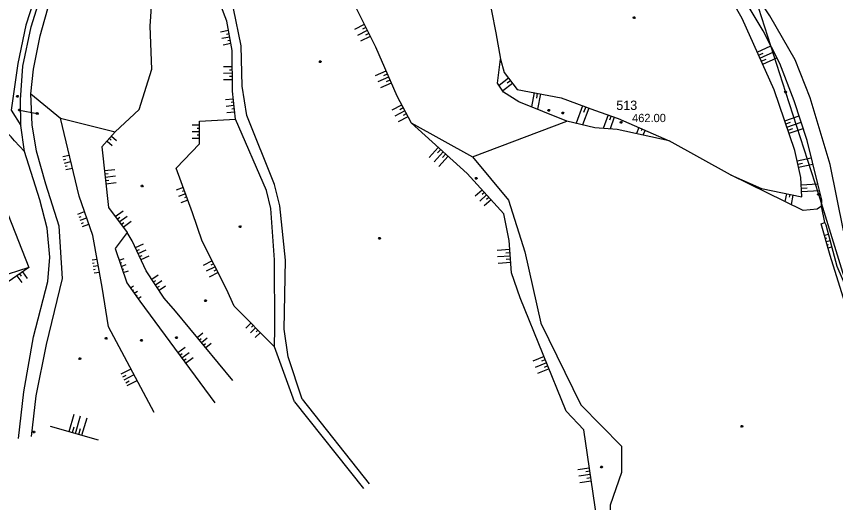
# Model space of a CAD drawing. Extents: x -664960 to -662754, y -993849 to -991145.
# Drawn here: x -664152.5 to -663855.3, y -993419.9 to -993243.5 of the extents above; entities that cross this region are included whole.
import ezdxf

# ---------------------------------------------------------------- set-up
doc = ezdxf.new("R2010")
doc.units = 0
for name, color, linetype in [('Vrstva 1', 7, 'Continuous'), ('Vrstva 13', 7, 'Continuous'), ('Vrstva 18', 7, 'Continuous'), ('Vrstva 23', 7, 'Continuous'), ('Vrstva 24', 7, 'Continuous'), ('Vrstva 27', 7, 'Continuous'), ('Vrstva 28', 7, 'Continuous'), ('Vrstva 33', 7, 'Continuous'), ('Vrstva 37', 7, 'Continuous'), ('Vrstva 57', 7, 'Continuous'), ('Vrstva 63', 7, 'Continuous'), ('Vrstva 8', 7, 'Continuous')]:
    doc.layers.add(name, color=color, linetype=linetype)

msp = doc.modelspace()

# ---------------------------------------------------------------- linework, layer by layer
at = {"layer": 'Vrstva 13'}
for points in [[(-663928.242, -993243.658), (-663928.062, -993243.958), (-663928.242, -993244.258), (-663928.602, -993244.258), (-663928.782, -993243.958), (-663928.602, -993243.658), (-663928.242, -993243.658)], [(-664042.083, -993259.608), (-664041.903, -993259.908), (-664042.083, -993260.208), (-664042.443, -993260.208), (-664042.623, -993259.908), (-664042.443, -993259.608), (-664042.083, -993259.608)], [(-664151.891, -993272.22), (-664151.711, -993272.52), (-664151.891, -993272.82), (-664152.251, -993272.82), (-664152.431, -993272.52), (-664152.251, -993272.22), (-664151.891, -993272.22)], [(-663959.185, -993277.337), (-663959.005, -993277.637), (-663959.185, -993277.937), (-663959.545, -993277.937), (-663959.725, -993277.637), (-663959.545, -993277.337), (-663959.185, -993277.337)], [(-663954.102, -993278.318), (-663953.922, -993278.618), (-663954.102, -993278.918), (-663954.462, -993278.918), (-663954.642, -993278.618), (-663954.462, -993278.318), (-663954.102, -993278.318)], [(-663985.497, -993302.005), (-663985.317, -993302.305), (-663985.497, -993302.605), (-663985.857, -993302.605), (-663986.037, -993302.305), (-663985.857, -993302.005), (-663985.497, -993302.005)], [(-664106.7, -993304.738), (-664106.52, -993305.038), (-664106.7, -993305.338), (-664107.06, -993305.338), (-664107.24, -993305.038), (-664107.06, -993304.738), (-664106.7, -993304.738)], [(-664071.171, -993319.55), (-664070.991, -993319.85), (-664071.171, -993320.15), (-664071.531, -993320.15), (-664071.711, -993319.85), (-664071.531, -993319.55), (-664071.171, -993319.55)], [(-664020.555, -993323.799), (-664020.375, -993324.099), (-664020.555, -993324.399), (-664020.915, -993324.399), (-664021.095, -993324.099), (-664020.915, -993323.799), (-664020.555, -993323.799)], [(-664106.935, -993360.698), (-664106.755, -993360.998), (-664106.935, -993361.298), (-664107.295, -993361.298), (-664107.475, -993360.998), (-664107.295, -993360.698), (-664106.935, -993360.698)], [(-664094.245, -993359.816), (-664094.065, -993360.116), (-664094.245, -993360.416), (-664094.605, -993360.416), (-664094.785, -993360.116), (-664094.605, -993359.816), (-664094.245, -993359.816)], [(-664129.266, -993367.383), (-664129.086, -993367.683), (-664129.266, -993367.983), (-664129.626, -993367.983), (-664129.806, -993367.683), (-664129.626, -993367.383), (-664129.266, -993367.383)], [(-663889.154, -993391.926), (-663888.974, -993392.226), (-663889.154, -993392.526), (-663889.514, -993392.526), (-663889.694, -993392.226), (-663889.514, -993391.926), (-663889.154, -993391.926)], [(-663940.049, -993406.702), (-663939.869, -993407.002), (-663940.049, -993407.302), (-663940.409, -993407.302), (-663940.589, -993407.002), (-663940.409, -993406.702), (-663940.049, -993406.702)]]:
    msp.add_lwpolyline(points, dxfattribs=at)
at = {"layer": 'Vrstva 18'}
msp.add_lwpolyline([(-664119.73, -993359.99), (-664119.55, -993360.29), (-664119.73, -993360.59), (-664120.09, -993360.59), (-664120.27, -993360.29), (-664120.09, -993359.99), (-664119.73, -993359.99)], dxfattribs=at)
at = {"layer": 'Vrstva 23'}
for points in [[(-663815.88, -993423.57), (-663819.75, -993405.36), (-663824.31, -993392.64), (-663830.79, -993376.07), (-663837.06, -993363.48), (-663843.01, -993348.71), (-663847.89, -993337.31), (-663852.5, -993321.23), (-663857.35, -993297.27), (-663864.53, -993273.11), (-663869.95, -993259.28), (-663879.15, -993243.34), (-663886.53, -993232.14), (-663892.56, -993221.84), (-663896.18, -993214.23), (-663900.17, -993200.79), (-663906.47, -993181.7), (-663914.77, -993161.34), (-663922.1, -993138.98)], [(-663822.04, -993421.3), (-663825.37, -993406.88), (-663827.71, -993398.5), (-663836.15, -993377.65), (-663841.61, -993365.19), (-663849.31, -993346.83), (-663854.8, -993334.21), (-663858.7, -993319.26), (-663859.27, -993318.31), (-663860.4, -993312.33), (-663860.36, -993310.06), (-663861.8, -993304.26), (-663865.7, -993288.6), (-663870.3, -993274.19), (-663875.56, -993260.56), (-663881.56, -993248.78), (-663891.79, -993231.72), (-663900.57, -993216.2), (-663905.55, -993200.84), (-663911.44, -993184.13), (-663916.56, -993171.4), (-663923.7, -993156.46)]]:
    msp.add_lwpolyline(points, dxfattribs=at)
at = {"layer": 'Vrstva 24'}
msp.add_line((-664151.4, -993277.48), (-664144.89, -993278.73), dxfattribs=at)
for points in [[(-664151.167, -993277.219), (-664151.046, -993277.548), (-664151.28, -993277.809), (-664151.633, -993277.741), (-664151.754, -993277.412), (-664151.52, -993277.151), (-664151.167, -993277.219)], [(-664144.657, -993278.469), (-664144.536, -993278.798), (-664144.77, -993279.059), (-664145.123, -993278.991), (-664145.244, -993278.662), (-664145.01, -993278.401), (-664144.657, -993278.469)]]:
    msp.add_lwpolyline(points, dxfattribs=at)
at = {"layer": 'Vrstva 27'}
for p, q in [((-664051.54, -993383.38), (-664026.58, -993414.83)), ((-664048.77, -993382.43), (-664024.46, -993413.09))]:
    msp.add_line(p, q, dxfattribs=at)
for points in [[(-664147.01, -993395.9), (-664145.28, -993381.2), (-664141.55, -993362.53), (-664135.78, -993338.59), (-664136.97, -993319.67), (-664141.74, -993304.41), (-664145.22, -993292.42), (-664146.78, -993282.88), (-664147.19, -993271.56), (-664146.28, -993262.65), (-664143.88, -993250.55), (-664140.16, -993237.45), (-664129.58, -993207.88), (-664122.4, -993183.29), (-664113.26, -993147.21), (-664109.07, -993129.57), (-664107.16, -993119.53), (-664106.79, -993108.69), (-664107.93, -993100.41), (-664112.62, -993085.27), (-664115.65, -993071.43)], [(-664051.54, -993383.38), (-664058.81, -993363.36), (-664058.78, -993356.49), (-664058.79, -993331.89), (-664060.13, -993313.2), (-664061.75, -993306.66), (-664073.02, -993280.85), (-664074.1, -993270.6), (-664074.16, -993255.88), (-664076.17, -993245.22), (-664085.19, -993221.44), (-664087.2, -993194.52), (-664081.52, -993180.73), (-664078.91, -993164.26)], [(-664048.77, -993382.43), (-664053.9, -993366.99), (-664055.33, -993357.04), (-664054.9, -993332.02), (-664056.86, -993312.19), (-664058.79, -993304.54), (-664068.83, -993279.47), (-664070.61, -993268.81), (-664070.96, -993254.16), (-664073.76, -993240.67), (-664079.2, -993222.98), (-664080.19, -993205.56), (-664079.44, -993193.25), (-664077.43, -993182.42)], [(-664151.67, -993396.63), (-664149.76, -993379.75), (-664146.27, -993359.81), (-664141.09, -993339.76), (-664140.31, -993330.82), (-664141.36, -993320.31), (-664143.91, -993310.04), (-664149.55, -993292.53), (-664150.84, -993283.04), (-664150.96, -993273.8), (-664150.15, -993261.61), (-664147.11, -993247.3), (-664143.19, -993234.78)]]:
    msp.add_lwpolyline(points, dxfattribs=at)
at = {"layer": 'Vrstva 28'}
msp.add_lwpolyline([(-664083.68, -993346.34), (-664083.5, -993346.64), (-664083.68, -993346.94), (-664084.04, -993346.94), (-664084.22, -993346.64), (-664084.04, -993346.34), (-664083.68, -993346.34)], dxfattribs=at)
at = {"layer": 'Vrstva 33'}
msp.add_lwpolyline([(-664145.96, -993394.07), (-664145.78, -993394.37), (-664145.96, -993394.67), (-664146.32, -993394.67), (-664146.5, -993394.37), (-664146.32, -993394.07), (-664145.96, -993394.07)], dxfattribs=at)
at = {"layer": 'Vrstva 37'}
for points in [[(-663873.3, -993270.68), (-663873.12, -993270.98), (-663873.3, -993271.28), (-663873.66, -993271.28), (-663873.84, -993270.98), (-663873.66, -993270.68), (-663873.3, -993270.68)], [(-663861.37, -993307.74), (-663861.19, -993308.04), (-663861.37, -993308.34), (-663861.73, -993308.34), (-663861.91, -993308.04), (-663861.73, -993307.74), (-663861.37, -993307.74)]]:
    msp.add_lwpolyline(points, dxfattribs=at)
at = {"layer": 'Vrstva 57'}
msp.add_lwpolyline([(-663937.17, -993067.28), (-663921.25, -993118.58), (-663905.79, -993167.82), (-663887.66, -993226.85), (-663873.48, -993270.98), (-663861.55, -993308.04), (-663843.55, -993366.56), (-663828.28, -993415.08), (-663809.04, -993475.6), (-663791.79, -993531.02), (-663772.5, -993592.28), (-663754.33, -993650.13), (-663735.8, -993708.15), (-663717.65, -993766.39)], dxfattribs=at)
at = {"layer": 'Vrstva 63'}
for p, q in [((-664026.288, -993246.492), (-664029.795, -993248.256)), ((-664025.748, -993247.564), (-664026.916, -993248.151)), ((-664075.52, -993248.668), (-664078.411, -993249.213)), ((-664075.075, -993251.026), (-664077.966, -993251.572)), ((-664075.298, -993249.847), (-664076.26, -993250.029)), ((-664025.209, -993248.636), (-664028.717, -993250.4)), ((-664024.131, -993250.78), (-664027.638, -993252.544)), ((-664024.67, -993249.708), (-664025.838, -993250.295)), ((-664074.63, -993253.385), (-664077.522, -993253.93)), ((-664074.853, -993252.206), (-664075.816, -993252.387)), ((-663883.748, -993256.465), (-663878.785, -993254.228)), ((-663883.255, -993257.559), (-663881.585, -993256.806)), ((-663882.761, -993258.653), (-663877.694, -993256.369)), ((-663882.268, -993259.747), (-663880.564, -993258.979)), ((-663881.775, -993260.841), (-663876.604, -993258.51)), ((-664074.136, -993261.763), (-664077.398, -993261.776)), ((-664074.131, -993262.963), (-664075.217, -993262.967)), ((-664074.126, -993264.163), (-664077.388, -993264.176)), ((-664074.121, -993265.363), (-664075.208, -993265.367)), ((-664018.417, -993263.373), (-664022.364, -993265.083)), ((-664017.463, -993265.575), (-664021.411, -993267.285)), ((-664017.94, -993264.474), (-664019.254, -993265.043)), ((-663974.005, -993265.912), (-663977.375, -993268.542)), ((-664074.116, -993266.563), (-664077.378, -993266.576)), ((-664016.509, -993267.778), (-664020.457, -993269.487)), ((-664016.986, -993266.676), (-664018.301, -993267.246)), ((-663972.529, -993267.804), (-663976.081, -993270.576)), ((-663973.267, -993266.858), (-663974.419, -993267.758)), ((-663964.695, -993271.182), (-663965.667, -993276.288)), ((-663963.517, -993271.406), (-663963.855, -993273.184)), ((-663962.338, -993271.631), (-663963.398, -993277.202)), ((-664073.796, -993273.481), (-664076.59, -993273.776)), ((-664073.671, -993274.675), (-664074.601, -993274.773)), ((-664073.545, -993275.868), (-664076.338, -993276.162)), ((-664073.419, -993277.062), (-664074.349, -993277.16)), ((-664012.752, -993275.68), (-664016.285, -993277.567)), ((-664011.621, -993277.796), (-664015.154, -993279.684)), ((-664012.186, -993276.738), (-664013.363, -993277.367)), ((-663947.088, -993275.937), (-663949.456, -993282.309)), ((-663944.838, -993276.773), (-663947.113, -993282.894)), ((-663945.963, -993276.355), (-663946.736, -993278.435)), ((-664073.293, -993278.255), (-664076.087, -993278.549)), ((-664010.49, -993279.913), (-664014.023, -993281.801)), ((-664011.055, -993278.855), (-664012.232, -993279.484)), ((-663937.883, -993279.237), (-663939.598, -993284.185)), ((-663936.749, -993279.63), (-663937.283, -993281.172)), ((-663935.615, -993280.023), (-663937.11, -993284.335)), ((-663873.742, -993281.394), (-663868.564, -993279.627)), ((-664086.065, -993283.022), (-664088.732, -993283.032)), ((-663986.99, -993294.52), (-663952.78, -993281.48)), ((-663873.354, -993282.53), (-663871.637, -993281.944)), ((-663872.966, -993283.665), (-663867.834, -993281.914)), ((-664086.056, -993285.422), (-664088.723, -993285.432)), ((-664086.06, -993284.222), (-664086.949, -993284.225)), ((-664086.052, -993286.622), (-664086.94, -993286.625)), ((-663926.639, -993283.864), (-663927.605, -993286.044)), ((-663925.542, -993284.35), (-663925.832, -993285.004)), ((-663924.445, -993284.837), (-663925.217, -993286.58)), ((-663872.579, -993284.801), (-663870.877, -993284.22)), ((-663872.191, -993285.937), (-663867.104, -993284.2)), ((-664119.538, -993288.723), (-664117.702, -993290.361)), ((-664118.739, -993287.828), (-664118.127, -993288.373)), ((-664117.94, -993286.932), (-664116.104, -993288.57)), ((-664086.047, -993287.822), (-664088.715, -993287.832)), ((-663999.454, -993291.042), (-664002.765, -993294.704)), ((-663997.674, -993292.652), (-664000.985, -993296.313)), ((-663998.564, -993291.847), (-663999.667, -993293.066)), ((-664135.595, -993294.369), (-664133.269, -993293.847)), ((-664135.333, -993295.54), (-664134.554, -993295.365)), ((-663995.894, -993294.262), (-663999.204, -993297.923)), ((-663996.784, -993293.457), (-663997.886, -993294.676)), ((-663869.256, -993295.919), (-663864.153, -993294.813)), ((-664135.07, -993296.711), (-664132.717, -993296.183)), ((-664134.808, -993297.882), (-664134.02, -993297.705)), ((-664134.545, -993299.053), (-664132.165, -993298.519)), ((-663869.002, -993297.092), (-663867.291, -993296.721)), ((-663868.748, -993298.265), (-663863.573, -993297.143)), ((-664120.534, -993299.442), (-664116.809, -993299.035)), ((-664120.403, -993300.635), (-664119.163, -993300.5)), ((-664120.273, -993301.828), (-664116.548, -993301.42)), ((-664120.142, -993303.021), (-664118.902, -993302.885)), ((-664120.012, -993304.214), (-664116.287, -993303.806)), ((-663867.791, -993304.602), (-663861.8, -993304.26)), ((-664091.92, -993305.634), (-664094.542, -993306.604)), ((-664091.504, -993306.759), (-664092.377, -993307.082)), ((-663983.544, -993306.504), (-663986.023, -993308.751)), ((-663982.738, -993307.393), (-663983.564, -993308.141)), ((-663867.722, -993305.8), (-663865.652, -993305.682)), ((-663867.654, -993306.998), (-663861.212, -993306.63)), ((-664091.087, -993307.885), (-664093.709, -993308.855)), ((-664090.254, -993310.135), (-664092.876, -993311.106)), ((-664090.671, -993309.01), (-664091.544, -993309.333)), ((-663981.932, -993308.282), (-663984.411, -993310.529)), ((-663980.32, -993310.06), (-663982.799, -993312.307)), ((-663981.126, -993309.171), (-663981.952, -993309.92)), ((-663873.14, -993307.846), (-663873.716, -993310.663)), ((-663871.965, -993308.086), (-663872.177, -993309.126)), ((-663870.789, -993308.326), (-663871.488, -993311.751)), ((-664130.152, -993315.234), (-664127.772, -993314.333)), ((-664129.728, -993316.356), (-664128.943, -993316.059)), ((-664116.631, -993316.164), (-664113.754, -993314.016)), ((-664115.913, -993317.125), (-664114.955, -993316.41)), ((-664115.195, -993318.087), (-664112.318, -993315.939)), ((-664129.303, -993317.479), (-664126.971, -993316.596)), ((-664128.878, -993318.601), (-664128.11, -993318.31)), ((-664128.453, -993319.723), (-664126.171, -993318.859)), ((-664114.477, -993319.048), (-664113.519, -993318.333)), ((-664113.759, -993320.01), (-664110.882, -993317.862)), ((-663859.368, -993322.895), (-663857.862, -993322.472)), ((-663859.044, -993324.05), (-663858.55, -993323.911)), ((-663858.72, -993325.205), (-663857.256, -993324.795)), ((-664109.277, -993327.427), (-664106.38, -993326.078)), ((-664108.771, -993328.515), (-664107.806, -993328.066)), ((-664108.264, -993329.603), (-664105.367, -993328.254)), ((-663973.489, -993328.067), (-663978.144, -993328.419)), ((-663858.396, -993326.361), (-663857.915, -993326.226)), ((-663858.072, -993327.516), (-663856.65, -993327.117)), ((-664115.243, -993331.937), (-664113.402, -993331.31)), ((-664107.757, -993330.69), (-664106.793, -993330.241)), ((-664107.251, -993331.778), (-664104.354, -993330.429)), ((-663973.307, -993330.46), (-663977.963, -993330.813)), ((-663973.398, -993329.263), (-663974.948, -993329.381)), ((-664125.014, -993331.817), (-664123.171, -993331.545)), ((-664124.838, -993333.004), (-664124.212, -993332.912)), ((-664124.663, -993334.191), (-664122.746, -993333.908)), ((-664114.857, -993333.073), (-664114.243, -993332.864)), ((-664114.47, -993334.209), (-664112.629, -993333.583)), ((-664081.453, -993332.196), (-664084.731, -993333.874)), ((-664080.36, -993334.332), (-664083.638, -993336.01)), ((-664080.906, -993333.264), (-664081.998, -993333.823)), ((-663973.126, -993332.853), (-663977.781, -993333.206)), ((-663973.217, -993331.657), (-663974.767, -993331.774)), ((-664151.282, -993336.921), (-664150.711, -993337.733)), ((-664150.301, -993336.231), (-664148.585, -993338.67)), ((-664124.488, -993335.378), (-664123.837, -993335.282)), ((-664124.312, -993336.565), (-664122.321, -993336.271)), ((-664114.084, -993335.345), (-664113.471, -993335.136)), ((-664113.698, -993336.481), (-664111.856, -993335.855)), ((-664103.348, -993338.881), (-664101.013, -993337.333)), ((-664079.266, -993336.469), (-664082.544, -993338.147)), ((-664079.813, -993335.401), (-664080.905, -993335.959)), ((-664152.264, -993337.611), (-664150.548, -993340.051)), ((-664102.686, -993339.881), (-664101.908, -993339.366)), ((-664102.023, -993340.882), (-664099.687, -993339.334)), ((-664111.109, -993342.023), (-664109.994, -993341.225)), ((-664110.41, -993342.999), (-664110.039, -993342.733)), ((-664109.712, -993343.974), (-664108.597, -993343.176)), ((-664101.36, -993341.882), (-664100.582, -993341.367)), ((-664100.697, -993342.882), (-664098.362, -993341.335)), ((-664109.013, -993344.95), (-664108.642, -993344.684)), ((-664108.315, -993345.926), (-664107.2, -993345.127)), ((-664067.376, -993354.77), (-664069.288, -993356.676)), ((-664065.682, -993356.47), (-664067.593, -993358.376)), ((-664066.529, -993355.62), (-664067.165, -993356.255)), ((-664064.834, -993357.319), (-664065.471, -993357.954)), ((-664086.843, -993359.993), (-664084.855, -993358.347)), ((-664086.078, -993360.917), (-664085.416, -993360.369)), ((-664085.313, -993361.841), (-664083.325, -993360.195)), ((-664063.987, -993358.169), (-664065.898, -993360.075)), ((-664093.931, -993365.491), (-664091.194, -993363.476)), ((-664084.548, -993362.766), (-664083.886, -993362.218)), ((-664083.783, -993363.69), (-664081.794, -993362.044)), ((-664093.22, -993366.457), (-664092.308, -993365.786)), ((-664092.508, -993367.424), (-664089.771, -993365.409)), ((-663961.07, -993366.96), (-663965.204, -993368.635)), ((-664091.797, -993368.39), (-664090.885, -993367.719)), ((-664091.085, -993369.356), (-664088.349, -993367.342)), ((-663960.169, -993369.185), (-663964.303, -993370.859)), ((-663960.62, -993368.073), (-663961.996, -993368.63)), ((-664114.445, -993373.206), (-664110.864, -993371.393)), ((-663959.268, -993371.409), (-663963.402, -993373.084)), ((-663959.719, -993370.297), (-663961.095, -993370.855)), ((-664113.903, -993374.277), (-664112.703, -993373.669)), ((-664113.36, -993375.347), (-664109.736, -993373.511)), ((-664112.818, -993376.418), (-664111.604, -993375.803)), ((-664112.276, -993377.488), (-664108.607, -993375.63)), ((-664133.311, -993394.19), (-664131.461, -993387.788)), ((-664131.006, -993394.857), (-664129.156, -993388.454)), ((-664128.7, -993395.523), (-664126.85, -993389.12)), ((-664140.2, -993392.2), (-664122.86, -993397.21)), ((-664132.158, -993394.523), (-664131.542, -993392.391)), ((-664129.853, -993395.19), (-664129.237, -993393.057)), ((-663944.663, -993407.384), (-663948.851, -993407.999)), ((-663944.488, -993408.571), (-663945.883, -993408.776)), ((-663944.314, -993409.758), (-663948.502, -993410.373)), ((-663944.14, -993410.945), (-663945.534, -993411.15)), ((-663943.965, -993412.133), (-663948.153, -993412.748))]:
    msp.add_line(p, q, dxfattribs=at)
for points in [[(-664130.678, -993066.532), (-664125.037, -993071.808), (-664119.18, -993086.85), (-664114.57, -993099.61), (-664113.25, -993107.22), (-664114.08, -993121.25), (-664117.42, -993139.12), (-664123.32, -993165.24), (-664133.21, -993201.92), (-664135.82, -993209.56), (-664144.89, -993233.81), (-664149, -993246.64), (-664152, -993260.56), (-664154.41, -993277.57), (-664150.84, -993283.04)], [(-664147.19, -993271.56), (-664136.43, -993280.47), (-664116.6, -993285.43), (-664107.88, -993277.26), (-664103.4, -993262.64), (-664104, -993247.07), (-664103.02, -993232.82), (-664103.36, -993202.59), (-664101.44, -993179.46), (-664097.78, -993160.43), (-664095.21, -993131.12), (-664094.64, -993113.28), (-664098.78, -993105.89), (-664107.93, -993100.41)], [(-663893.5, -993301), (-663882.23, -993305.99), (-663867.54, -993308.99), (-663867.94, -993301.99), (-663870.08, -993292.12), (-663877.58, -993270.15), (-663889.23, -993244.3), (-663900.01, -993225.23), (-663907.39, -993207.04), (-663913.2, -993189.62), (-663915.1, -993182.61)], [(-664027.74, -993201.66), (-664028.21, -993209.93), (-664029.15, -993240.8), (-664022.26, -993254.5), (-664014.52, -993272.37), (-664009.3, -993282.14), (-663986.99, -993294.52), (-663973.93, -993310.19), (-663967.99, -993328.89), (-663962.3, -993354.8), (-663947.76, -993384.44), (-663933.03, -993399.51), (-663933.03, -993408.97), (-663937.13, -993420.91), (-663936.54, -993450.22), (-663931.92, -993484.71), (-663931.46, -993505.55), (-663930.01, -993521.07)], [(-663983.33, -993225.46), (-663978.52, -993249.41), (-663976.91, -993259.08)], [(-663860.4, -993312.33), (-663862.06, -993313.48), (-663867.11, -993313.89), (-663893.5, -993301), (-663915.68, -993288.72), (-663934.53, -993284.49), (-663942.68, -993284), (-663952.78, -993281.48), (-663970.18, -993274.47), (-663975.83, -993270.97), (-663977.91, -993267.7), (-663976.91, -993259.08), (-663975.56, -993263.92), (-663970.8, -993270.02), (-663954.83, -993273.06), (-663942.72, -993277.56), (-663934.21, -993280.51), (-663915.68, -993288.72)], [(-664149.55, -993292.53), (-664153.17, -993288.63), (-664154.4, -993287.22), (-664159.92, -993281.66), (-664169.74, -993280.29), (-664159.28, -993305.93), (-664148.01, -993334.62), (-664155.45, -993337.05), (-664170.48, -993339.49), (-664179.92, -993342.03)], [(-664102.45, -993387.19), (-664119.01, -993356.1), (-664121.33, -993341.78), (-664124.71, -993322.99), (-664129.75, -993308.74), (-664136.43, -993280.47)], [(-664058.81, -993363.36), (-664073.45, -993348.68), (-664076.21, -993342.44), (-664085.08, -993325.11), (-664088.55, -993314.74), (-664094.52, -993298.61), (-664086.04, -993289.79), (-664086.07, -993281.56), (-664073.02, -993280.85)], [(-663931.46, -993505.55), (-663936.16, -993485.44), (-663940.59, -993452.38), (-663941.97, -993425.71), (-663946.7, -993393.52), (-663953.05, -993386.76), (-663969.69, -993345.68), (-663972.85, -993336.5), (-663973.73, -993324.88), (-663975.68, -993315.18), (-663988.95, -993300.54), (-664009.3, -993282.14)], [(-664116.6, -993285.43), (-664121.47, -993290.89), (-664119.06, -993312.91), (-664112.34, -993321.91), (-664116.68, -993327.71), (-664112.45, -993340.15), (-664107.66, -993346.84), (-664080.49, -993383.75)], [(-663803.57, -993521.02), (-663807.14, -993513.56), (-663812.1, -993497.55), (-663815.91, -993484.44), (-663820.6, -993473.24), (-663824.2, -993457.61), (-663826.12, -993443.73), (-663830.59, -993414.91), (-663841.03, -993379.83), (-663850.21, -993353.11), (-663857.31, -993330.23), (-663860.52, -993318.79), (-663859.27, -993318.31)], [(-664073.94, -993375.58), (-664094.71, -993350.49), (-664098.83, -993345.7), (-664105.35, -993335.86), (-664110.44, -993324.93), (-664112.34, -993321.91)], [(-664148.01, -993334.62), (-664158.22, -993341.8), (-664170.48, -993339.49), (-664181.97, -993346.29), (-664195.34, -993342.39)]]:
    msp.add_lwpolyline(points, dxfattribs=at)
at = {"layer": 'Vrstva 8'}
msp.add_lwpolyline([(-663932.97, -993281.68), (-663932.79, -993281.98), (-663932.97, -993282.28), (-663933.33, -993282.28), (-663933.51, -993281.98), (-663933.33, -993281.68), (-663932.97, -993281.68)], dxfattribs=at)

# ---------------------------------------------------------------- texts
at = {"layer": 'Vrstva 1'}
msp.add_text('513', height=3.4, dxfattribs=at).set_placement((-663934.882, -993277.462))
at = {"layer": 'Vrstva 63'}
msp.add_text('462.00', height=3, dxfattribs=at).set_placement((-663929.158, -993281.869))

doc.saveas('drawing.dxf')
